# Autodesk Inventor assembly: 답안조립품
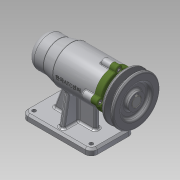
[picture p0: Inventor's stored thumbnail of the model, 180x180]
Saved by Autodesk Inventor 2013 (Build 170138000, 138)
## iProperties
Created: 2019-07
Part Number: 답안조립품
Document SubType Name: Assembly
Designer: Administrator
Author: Administrator
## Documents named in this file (12)
- C:\Users\Administrator\Desktop\490704V1035\답안조립품.iam
- C:\Users\Administrator\Desktop\490704V1035\본체.ipt
- C:\Users\Administrator\Desktop\490704V1035\V벨트풀리.ipt
- C:\Users\Administrator\Desktop\490704V1035\멈춤나사 M3.ipt
- C:\Users\Administrator\Desktop\490704V1035\베어링 6004.ipt
- C:\Users\Administrator\Desktop\490704V1035\베어링 51202.ipt
- C:\Users\Administrator\Desktop\490704V1035\볼트 M4.ipt
- C:\Users\Administrator\Desktop\490704V1035\어댑터슬리브.ipt
- C:\Users\Administrator\Desktop\490704V1035\오일 실.ipt
- C:\Users\Administrator\Desktop\490704V1035\축.ipt
- C:\Users\Administrator\Desktop\490704V1035\커버.ipt
- C:\Users\Administrator\Desktop\490704V1035\키 5 x 5 x 16.ipt
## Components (1 placed, 1 different names)
1. V벨트풀리:1
